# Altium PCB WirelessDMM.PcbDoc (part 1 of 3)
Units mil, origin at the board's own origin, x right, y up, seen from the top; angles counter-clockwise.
Board outline 6000 x 520 mil, 6 copper layers (Layer 1 - Top Layer, Layer 2 - GND, Layer 3 - Signal, Layer 4 - PWR, Layer 5 - GND, Layer 6 - Bottom Layer), stack 63.468 mil thick; 198 components, 117 nets, 636 pads, 272 vias.
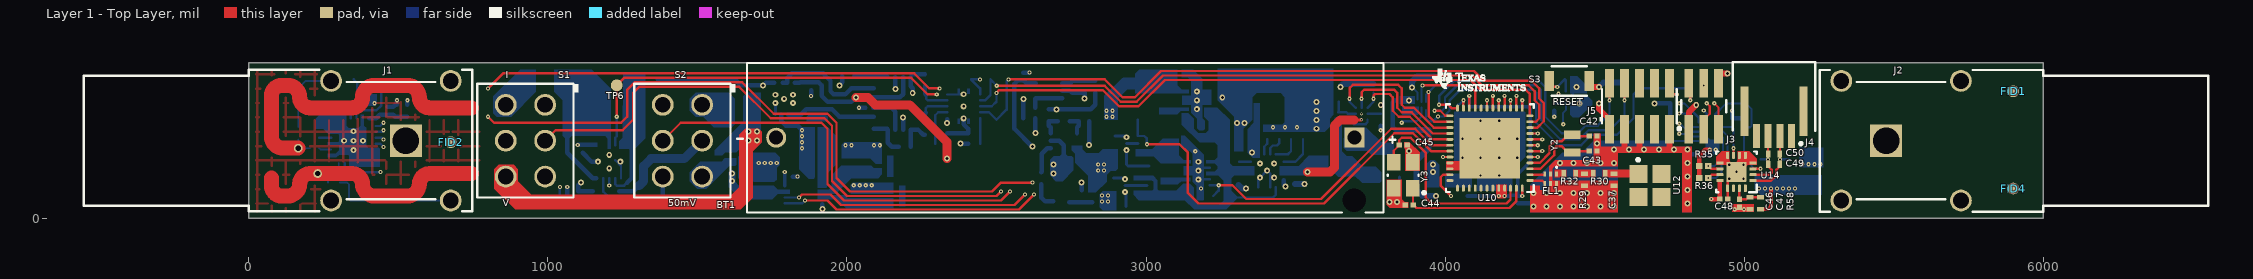
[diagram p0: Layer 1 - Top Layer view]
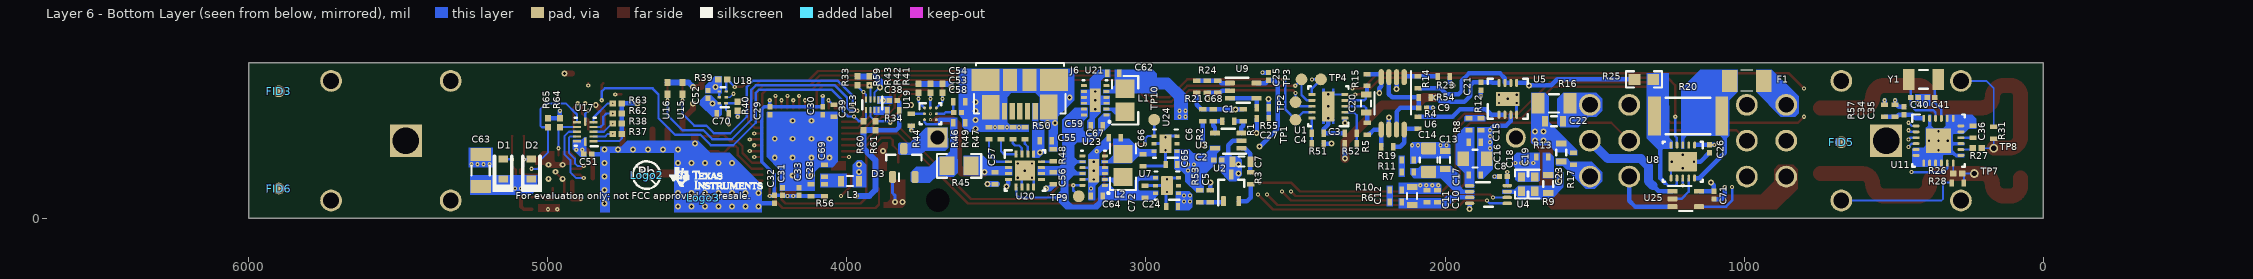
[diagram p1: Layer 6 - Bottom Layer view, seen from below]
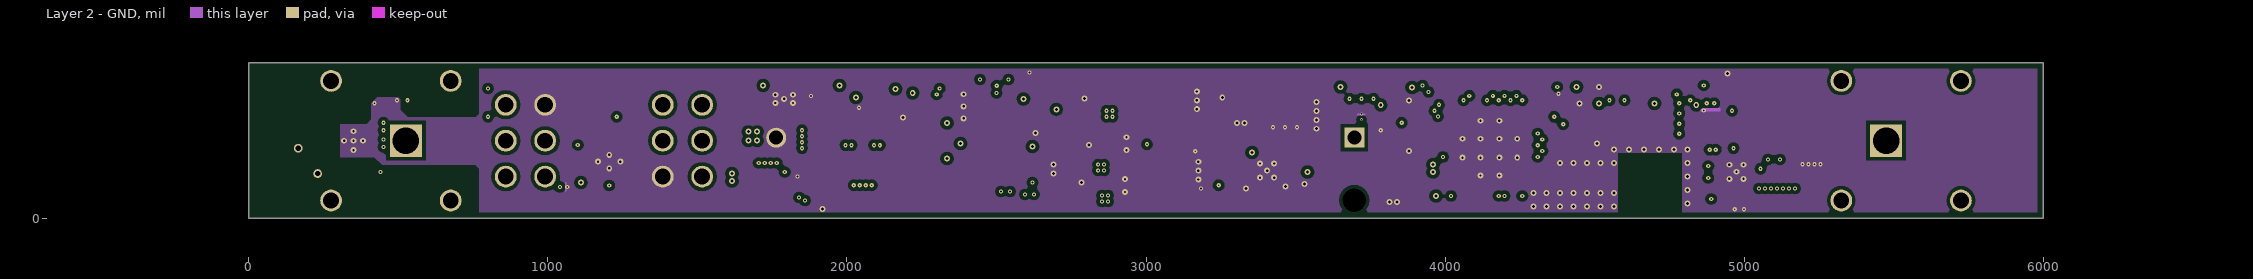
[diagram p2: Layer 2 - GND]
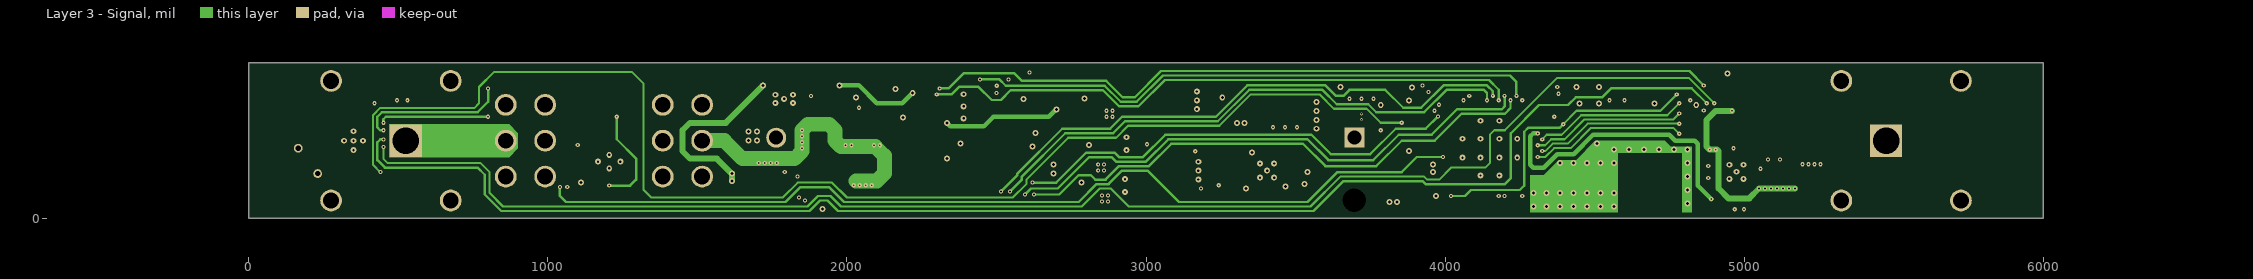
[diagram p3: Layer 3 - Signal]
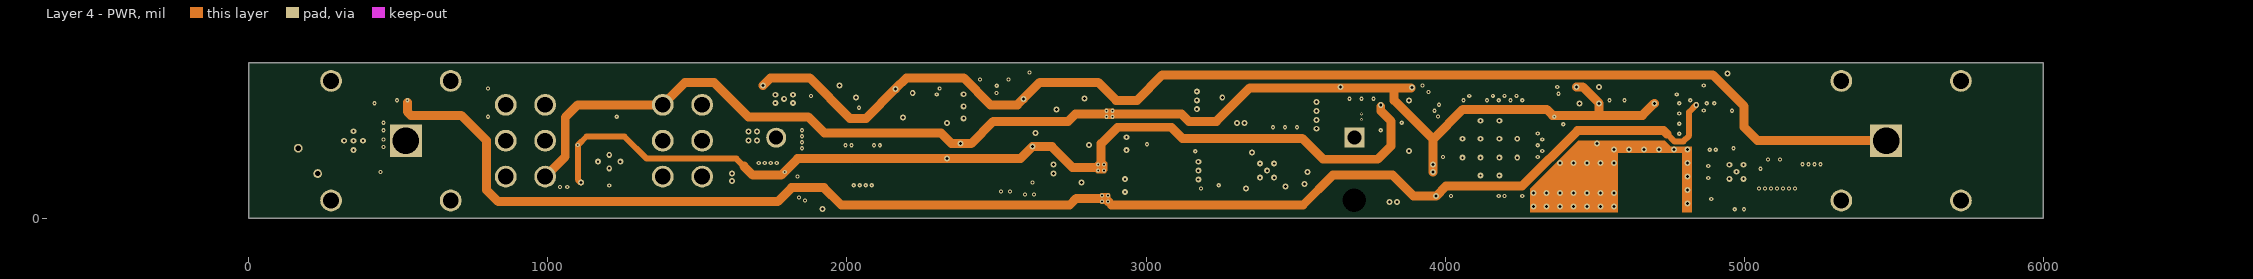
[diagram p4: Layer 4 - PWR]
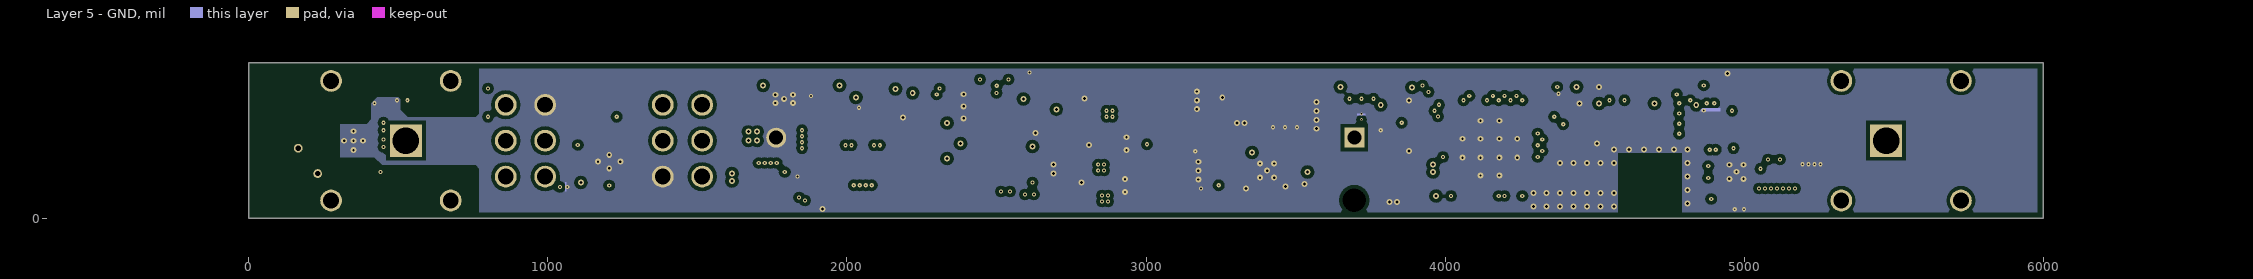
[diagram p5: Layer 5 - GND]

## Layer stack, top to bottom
Top Solder: solder mask 0.4, Solder Resist, Dk 3.5
Layer 1 - Top Layer: signal copper 1.4
Dielectric 1: prepreg 15, 370HR, Dk 4.2
Layer 2 - GND: signal copper 1.417
Dielectric 2: core 10, 370HR, Dk 4.2
Layer 3 - Signal: signal copper 1.417
Dielectric 3: prepreg 5, 370HR, Dk 4.2
Layer 4 - PWR: signal copper 1.417
Dielectric 4: core 10, 370HR, Dk 4.2
Layer 5 - GND: signal copper 1.417
Dielectric 5: prepreg 15, 370HR, Dk 4.2
Layer 6 - Bottom Layer: signal copper 1.4
Bottom Solder: solder mask 0.4, Solder Resist, Dk 3.5

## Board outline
0,0 0,520 6000,520 6000,0

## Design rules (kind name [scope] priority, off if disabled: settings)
AcuteAngle [All] p1: minimum=4.50000000000000E+0001 checktracksonly=FALSE
AssemblyTestPointUsage [All] p1: valid=2
BoardOutlineClearance BoardOutlineClearance_MountingHoles [OnCopper and InComponentClass('Mounting Holes')] p1: gap=40
BoardOutlineClearance BoardOutlineClearance_Poly [OnCopper and InPoly] p2: gap=20
BoardOutlineClearance [OnCopper and Not InComponentClass('Logo') and not InComponentClass('FiducialMark') and not InRegion(1000,500,4000,800)] p3: gap=19
Clearance Clearance_Keepouts [((IsTrack Or IsArc) And Not InPoly) And IsFree and IsKeepOut vs ((IsTrack Or IsArc) And Not InPoly) And IsFree and IsKeepOut] p1: gap=0
Clearance Clearance_Poly [InPolygon] p2: gap=12
Clearance [All] p3: gap=6
ComponentClearance ComponentClearance_MountingHoles_FiducialMarks [InComponentClass('Mounting Holes') vs InComponentClass('FiducialMark')] p1: gap=5 collisioncheckmode=3 verticalgap=10 showdistances=FALSE
ComponentClearance ComponentClearance_Shunt [InComponentClass('Header') vs InComponentClass('Shunt')] p2: gap=0 collisioncheckmode=3 verticalgap=0 showdistances=FALSE
ComponentClearance ComponentClearance_Logo [InComponentClass('Logo')] p3: gap=5 collisioncheckmode=3 verticalgap=10 showdistances=FALSE
ComponentClearance ComponentClearance_ScrewToNut [(HasFootprint('NY PMS 440 0025 PH')) vs (HasFootprint('Keystone_1902C'))] p4: gap=5 collisioncheckmode=3 verticalgap=10 showdistances=FALSE
ComponentClearance ComponentClearance_MountingHoles [InComponentClass('Mounting Holes')] p5: gap=5 collisioncheckmode=3 verticalgap=100000 showdistances=FALSE
ComponentClearance ComponentClearance_SmallPassives [HasFootprint('0201*') or HasFootprint('0402*') or HasFootprint('0508') or HasFootprint('0603*') or HasFootprint('0612') or HasFootprint('0805*') or HasFootprint('0815*') or HasFootprint('0830*') or HasFootprint('1206*') or HasFootprint('1210*') or HasFootprint('1808*') or HasFootprint('1812*') or HasFootprint('1825*') or HasFootprint('2010*') or HasFootprint('2220*') or HasFootprint('2225*') or HasFootprint('2512*') or HasFootprint('2728*') or HasFootprint('3518*') vs HasFootprint('0201*') or HasFootprint('0402*') or HasFootprint('0508') or HasFootprint('0603*') or HasFootprint('0612') or HasFootprint('0805*') or HasFootprint('0815*') or HasFootprint('0830*') or HasFootprint('1206*') or HasFootprint('1210*') or HasFootprint('1808*') or HasFootprint('1812*') or HasFootprint('1825*') or HasFootprint('2010*') or HasFootprint('2220*') or HasFootprint('2225*') or HasFootprint('2512*') or HasFootprint('2728*') or HasFootprint('3518*')] p6: gap=5 collisioncheckmode=3 verticalgap=10 showdistances=FALSE
ComponentClearance ComponentClearance_THtoSMT [IsThruComponent vs IsSMTComponent] p7: gap=5 collisioncheckmode=3 verticalgap=30 showdistances=FALSE
ComponentClearance ComponentClearance_THtoTH [IsThruComponent vs IsThruComponent] p8: gap=5 collisioncheckmode=3 verticalgap=30 showdistances=FALSE
ComponentClearance [All] p9: gap=5 collisioncheckmode=3 verticalgap=10 showdistances=FALSE
DiffPairsRouting [All] p1: maxlimit=100 minlimit=10 mostfreqgap=10 toplayer_minwidth=15 toplayer_maxwidth=15 toplayer_prefwidth=15 midlayer1_minwidth=15 midlayer1_maxwidth=15 midlayer1_prefwidth=15 midlayer2_minwidth=15 midlayer2_maxwidth=15 midlayer2_prefwidth=15 midlayer3_minwidth=15 midlayer3_maxwidth=15 midlayer3_prefwidth=15 midlayer4_minwidth=15 midlayer4_maxwidth=15 midlayer4_prefwidth=15 bottomlayer_minwidth=15 bottomlayer_maxwidth=15 bottomlayer_prefwidth=15 maxuncoupledlength=1000
FabricationTestPointUsage TestPointUsage [All] p1: valid=2 allowmultiple=FALSE
FabricationTestpoint Testpoint [All] p1: side=3 testpointundercomponent=TRUE minsize=40 maxsize=100 preferedsize=60 minholesize=0 maxholesize=40 preferedholesize=32 testpointgrid=1 allowsidetop=TRUE allowsidebottom=TRUE usegrid=TRUE gridtolerance=0.01
FanoutControl Fanout_LCC [IsLCC] p1: bgadir=Out bgaviamode=Centered fanoutstyle=Auto fanoutdirection=Alternating viagrid=1 // Fanout_LCC (Default Rule)
FanoutControl Fanout_BGA [IsBGA] p2: bgadir=Out bgaviamode=Centered fanoutstyle=Auto fanoutdirection=Alternating viagrid=1 // Fanout_BGA (Default Rule)
FanoutControl Fanout_Default [All] p4: bgadir=Out bgaviamode=Centered fanoutstyle=Auto fanoutdirection=Alternating viagrid=1 // Fanout_Default (Default Rule)
FanoutControl Fanout_Small [(CompPinCount < 5)] p5: bgadir=Out bgaviamode=Centered fanoutstyle=Auto fanoutdirection=OutThenIn viagrid=1 // Fanout_Small (Default Rule)
HoleSize [All] p1: absolutevalues=TRUE maxlimit=251 minlimit=6 maxpercent=80.000 minpercent=20.000
MinimumAnnularRing MinimumAnnularRing_ThermalPadVias [IsVia and InAnyComponent] p1: minimumring=5.91
MinimumAnnularRing [All] p2: minimumring=2
MinimumSolderMaskSliver MinimumSolderMaskSliver_Logo [InComponentClass('Logo') vs InComponentClass('Logo')] p1: minsoldermaskwidth=0.7
MinimumSolderMaskSliver [All] p2: minsoldermaskwidth=3.9
NetAntennae [All] p1 off: netantennaetolerance=0
PlaneConnect [All] p1: planeconnectstyle=Relief reliefexpansion=10 reliefentries=4 reliefconductorwidth=10 reliefairgap=10
PolygonConnect [All] p1: connectstyle=Direct reliefconductorwidth=10 reliefentries=4 polygonreliefangle="90 Angle" airgapwidth=10
RoutingVias ThermalPadVias [IsVia and InAnyComponent] p1: holewidth=7.87 width=19.68 viastyle="Through Hole" minholewidth=7.87 minwidth=19.68 maxholewidth=12.99 maxwidth=23.62
RoutingVias [All] p2: holewidth=16 width=34 viastyle="Through Hole" minholewidth=6 minwidth=10 maxholewidth=40 maxwidth=65
SilkToBoardRegionClearance [Not ((IsComment or IsDesignator) And (Hide <> 'False')) and not InRegion(1000,500,4000,800)] p1:
SilkToSilkClearance SilkToSilkClearance_Pb-FreeLogo [(HasFootprint('Pb-Free_Overlay_Medium') OR HasFootprint('Pb-Free_Overlay_Small')) vs (HasFootprint('Pb-Free_Overlay_Medium') OR HasFootprint('Pb-Free_Overlay_Small'))] p1: silktosilkclearance=0
SilkToSilkClearance [All] p2: silktosilkclearance=0.5
SilkToSolderMaskClearance SilkToComponentPadClearance [IsPad and InAnycomponent] p1: minsilkscreentomaskgap=3 clearancetoexposedcopper=TRUE
SilkToSolderMaskClearance "Silk to Solder Mask Opening" [All] p2: minsilkscreentomaskgap=4 clearancetoexposedcopper=FALSE
SolderMaskExpansion [All] p1: expansion=1.97
Width [All] p1: maxlimit=100 minlimit=6 preferedwidth=10 checkconnectedcopper=TRUE
14 further rules are at their usual default settings.

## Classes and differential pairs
component class AssemblyNote: ZZ2 ZZ3 ZZ4
component class FiducialMark: FID1 FID2 FID3 FID4 FID5 FID6
component class WirelessDMM_Hardware: FID1 FID2 FID3 FID4 FID5 FID6 Logo2 Logo3 ZZ2 ZZ3 ZZ4
component class Header: J3 J5
component class WirelessDMM_AFE: C1 C2 C3 C4 C5 C6 C7 C8 C9 C10 C11 C12 C13 C14 C15 C16 C17 C18 C19 C20 C21 C22 C23 C25 C26 C27 C68 C71 C? F1 J1 J2 R1 R2 R3 R4 R5 R6 R7 R8 R9 R10 R11 R12 R13 R14 R15 R16 R17 R19 R20 R21 R23 R24 R25 R28 R31 R51 R52 R53 R54 R55 S1 S2 TP1 TP2 TP3 TP4 TP6 U1 U2 U3 U4 U5 U6 U8 U9 U25
component class WirelessDMM_MCU: C28 C29 C30 C31 C32 C33 C34 C35 C36 C37 C38 C39 C40 C41 C42 C43 C44 C45 C46 C47 C48 C49 C50 C51 C52 C69 C70 FL1 J3 J4 J5 L3 R26 R27 R29 R30 R32 R33 R34 R35 R36 R37 R38 R39 R40 R56 R57 R58 R59 R60 R61 R62 R63 R64 R65 S3 TP7 TP8 U10 U11 U12 U13 U14 U15 U16 U17 U18 Y1 Y2 Y3
component class WirelessDMM_PWR: BT1 C24 C53 C54 C55 C56 C57 C58 C59 C62 C63 C64 C65 C66 C67 C72 D1 D2 D3 J6 L1 L2 R41 R42 R43 R44 R45 R46 R47 R48 R49 R50 TP9 TP10 U7 U19 U20 U21 U23 U24

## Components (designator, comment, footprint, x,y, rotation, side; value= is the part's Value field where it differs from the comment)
BT1 "1021" Keystone_1021 2730,270 r180 top locked
C1 "GRM155R71C104JA88D" 0402S 2725,325 r0 bottom
C2 "CL03A104KP3NNNC" 0201 2760,195 r0 bottom
C3 "GRM155R61A105KE15D" 0402S 2315,285 r180 bottom
C4 "GRM155R61A105KE15D" 0402S 2425,285 r0 bottom
C5 "C1005X5R0J105M050BB" 0402S 2785,75 r90 bottom
C6 "GRM155R60J226ME11D" 0402S 2810,345 r270 bottom
C7 "GRM188R6YA475KE15D" 0603S#1 2681,190 r0 bottom
C8 "CL03A104KP3NNNC" 0201 1805,140 r180 bottom
C9 "CL03A104KP3NNNC" 0201 2075,370 r0 bottom
C10 "C0402C122J5GACTU" 0402S 2025,75 r270 bottom
C11 "C0402C122J5GACTU" 0402S 2060,75 r270 bottom
C12 "C0603C104J5RACTU" 0603S#1 2110,75 r270 bottom
C13 "C0603C100F5GAC7867" 0603S#1 2000,195 r270 bottom
C14 "C0805C103F1GACTU" 0805_HV1 2055,195 r270 bottom
C15 "GRM1555C1H331FA01J" 0402S 1900,255 r0 bottom
C16 "08055A471FAT2A" 0805_HV1 1900,200 r0 bottom
C17 "GRM1555C1H151JA01D" 0402S 1900,145 r0 bottom
C18 "Used in BOM report" 0402 1745,115 r270 bottom
C19 "Used in BOM report" 0402 1700,115 r270 bottom
C20 "GRM1885C1H222JA01D" 0603S#1 2264,384 r270 bottom
C21 "CL03A104KP3NNNC" 0201 1880,442 r90 bottom
C22 "C1608C0G2A101F080AA" 0603S#2 1575,345 r90 bottom
C23 "C1608X7R2A223K" 0603S#1 1611.38,220.21 r90 bottom
C24 "GRM155R61A105KE15D" 0402S 2913,40 r0 bottom
C25 "CL03A104KP3NNNC" 0201 2590,475 r270 bottom
C26 "CL03A104KP3NNNC" 0201 1116,233 r90 bottom
C27 "C1005X5R0J105M050BB" 0402S 2610,334.7 r0 bottom
C28 "GRM155R61A105KE15D" 0402S 4120,95 r90 bottom
C29 "CL03A104KP3NNNC" 0201 4258,360.35 r270 bottom
C30 "CL03A104KP3NNNC" 0201 4081,360 r270 bottom
C31 "CL03A104KP3NNNC" 0201 4215,90 r90 bottom
C32 "CL03A104KP3NNNC" 0201 4243,64 r270 bottom
C33 "CL03A104KP3NNNC" 0201 4160,90 r90 bottom
C34 "C1005X5R1A475K050BC" 0402S 495,360 r90 bottom
C35 "CL03A104KP3NNNC" 0201 465,360 r90 bottom
C36 "GRM155R61A105KE15D" 0402S 235,290 r90 bottom
C37 "GRM1555C1H390JA01D" 0402S 4565.13,130 r270 top
C38 "CL03A104KP3NNNC" 0201 3845,395 r180 bottom
C39 "C1005X5R0J105M050BB" 0402S 4043,360 r270 bottom
C40 "GCM0335C1E220JD03D" 0201_033 430.01,405 r180 bottom
C41 "GCM0335C1E220JD03D" 0201_033 375.01,405 r0 bottom
C42 "GRM0335C1H120JA01D" 0201 4495,275 r180 top
C43 "GRM0335C1H120JA01D" 0201 4495,225 r0 top
C44 "GRM0335C1H120JA01D" 0201 3880,45 r180 top
C45 "GRM0335C1H120JA01D" 0201 3860,245 r0 top
C46 "CL03A104KP3NNNC" 0201 4984.47,51.09 r270 top
C47 "GRM155R61A105KE15D" 0402S 5019.47,51.09 r270 top
C48 "GRM033R60J474KE90D" 0201_033 4932,65 r0 top
C49 "GRM1555C1H390JA01D" 0402S 5100,180 r180 top
C50 "GRM1555C1H390JA01D" 0402S 5100,215 r180 top
C51 "CL03A104KP3NNNC" 0201 4867,215 r0 bottom
C52 "CL03A104KP3NNNC" 0201 4465,415 r270 bottom
C53 "GRM033R60J474KE90D" 0201_033 3630,355 r180 bottom
C54 "GRM155R61C225KE11D" 0402S 3625,390 r180 bottom
C55 "GRM155R61A105KE15D" 0402S 3335,260 r0 bottom
C56 "C1005X5R1A475K050BC" 0402S 3310,135 r270 bottom
C57 "C1005X5R1A475K050BC" 0402S 3505,135 r270 bottom
C58 "GRM155R61A105KE15D" 0402S 3625,320 r180 bottom
C59 "CL05A106MP5NUNC" 0402S 3165,310 r0 bottom
C62 "CL05A106MP5NUNC" 0402S 3110,485.28 r0 bottom
C63 "C3216X5R1A107M160AC" 1206_190L 5225,160 r90 bottom
C64 "CL05A106MP5NUNC" 0402S 3165,75 r0 bottom
C65 "GRM155R61A105KE15D" 0402S 2914.74,180 r0 bottom
C66 "GRM155R61A105KE15D" 0402S 3010,195 r270 bottom
C67 "CL05A106MP5NUNC" 0402S 3105,270 r0 bottom
C68 "C1005X5R0J105M050BB" 0402S 2760,440 r270 bottom
C69 "GRM155R61A105KE15D" 0402S 4075,160 r90 bottom
C70 "CL05A225KQ5NNNC" 0402S 4415,350 r0 bottom
C71 "CL03A104KP3NNNC" 0201 1101,78 r90 bottom
C72 "GRM155R61A105KE15D" 0402S 3003,90 r90 bottom
D1 "CDBU0130L" SOD-523F 5150,165 r90 bottom
D2 "CDBU0130L" SOD-523F 5055,165 r90 bottom
D3 "SI2323DS" SOT-23 3860,176 r180 bottom
F1 "NANOSMDC020F-2" FUSE_NANO02 991,460 r0 bottom
FID1 "Fiducial" Fiducial10-20 5900,425 r0 top
FID2 "Fiducial" Fiducial10-20 675,255 r0 top
FID3 "Fiducial" Fiducial10-20 5900,425 r180 bottom
FID4 "Fiducial" Fiducial10-20 5900,100 r0 top
FID5 "Fiducial" Fiducial10-20 675,255 r180 bottom
FID6 "Fiducial" Fiducial10-20 5900,100 r180 bottom
FL1 "LFB182G45BG5D920" Murata_LFB182G45BG5D920 4353,133 r270 top
J1 "66.9040-22" Multi-Contact_66_9040-22 475,260 r180 top locked
J2 "66.9040-21" Multi-Contact_66_9040-21 5525,260 r0 top locked
J3 "20021121-00006C4LF" FCI_20021121-00006x4 4865,375 r90 top
J4 "HFW4R-1STE1LF" HFW4R-1STE1LF 5100,317 r180 top locked
J5 "20021121-00010C4LF" FCI_20021121-00010xxLF 4650,375 r90 top
J6 "0473460001" CONN_47346-0001 3422,520 r180 bottom locked
L1 "MLZ2012A2R2WT000" 0805M 3070,395 r90 bottom
L2 "MLZ2012A2R2WT000" 0805M 3077,177 r90 bottom
L3 "BLM18HE152SN1D" 0603S#1 3990,125 r0 bottom
Logo2 "Pb-Free Symbol" Pb-Free_Overlay_Small 4670,145 r180 bottom
Logo3 "FCC disclaimer" FCC_disclaimer 4480,70 r180 bottom
R1 "CRCW040213K3FKED" 0402S 2675,345 r90 bottom
R2 "CRCW04028R20JNED" 0402S 2775,345 r90 bottom
R3 "CRCW040210K0FKED" 0402S 2650,135 r90 bottom
R4 "CRCW04023K01FKED" 0402S 2090,320 r270 bottom
R5 "CRCW040252R3FKED" 0402S 2260,300 r90 bottom
R6 "CRCW04029K76FKED" 0402S 2165,55 r180 bottom
R7 "RG1005P-104-B-T5" 0402S 2125,155 r180 bottom
R8 "CRCW04021M00FKED" 0402S 1920,315 r270 bottom
R9 "CRCW0603100MJPEAHR" 0603S#1 1655,115 r270 bottom
R10 "CRCW040210R0FKED" 0402S 2165,95 r0 bottom
R11 "CRCW04020000Z0ED" 0402S 2125,195 r0 bottom
R12 "CRCW040210K2FKED" 0402S 1880,315 r90 bottom
R13 "CRCW04020000Z0ED" 0402S 1675,205 r180 bottom
R14 "CRCW04023K01FKED" 0402S 2090,455 r270 bottom
R15 "CRCW040252R3FKED" 0402S 2261,463 r270 bottom
R16 "CRHV1206AF10M0FKE5" 1206L 1636,385 r180 bottom
R17 "CRCW0402499KFKED" 0402S 1570,200 r90 bottom
R19 "CRCW0402133KFKED" 0402S 2193.39,240 r180 bottom
R20 "CRCW251295R3FKEG" 2512L 1187,343 r180 bottom
R21 "CRCW040211K3FKED" 0402S 2830,440 r270 bottom
R23 "CRCW0402133KFKED" 0402S 2005,475 r180 bottom
R24 "CRCW040213K3FKED" 0402S 2795,440 r90 bottom
R25 "RL0603FR-070R5L" 0603 1335,465 r180 bottom
R26 "CRCW0201909RFKED" 0201M 285,150 r0 bottom
R27 "CRCW0201909RFKED" 0201M 220,235 r0 bottom
R28 "MCR01MZPJ000" 0402S 285,119 r180 bottom
R29 "MCR01MZPJ000" 0402S 4466,130 r90 top
R30 "MCR01MZPJ000" 0402S 4515,150 r180 top
R31 "MCR01MZPJ000" 0402S 165,286 r270 bottom
R32 "MCR01MZPJ000" 0402S 4417,150 r180 top
R33 "RK73H1HTTC4702F" 0201M 3965,460 r90 bottom
R34 "CRCW0402200KFKED" 0402S 3845,360 r0 bottom
R35 "RK73H1HTTC4702F" 0201M 4865,175 r180 top
R36 "RK73H1HTTC4702F" 0201M 4865,135 r180 top
R37 "RK73H1HTTC4702F" 0201M 4768,283 r0 bottom
R38 "RK73H1HTTC4702F" 0201M 4768,317 r0 bottom
R39 "CRCW0201100KFKED" 0201M 4415,465 r0 bottom
R40 "CRCW02011K00FKED" 0201M 4365,375 r270 bottom
R41 "CRCW020110K0FKED" 0201M 3680.85,435 r90 bottom
R42 "CRCW020110K0FKED" 0201M 3720.85,435 r90 bottom
R43 "CRCW020110K0FKED" 0201M 3760.85,435 r90 bottom
R44 "ERJ-2RKF1002X" 0402S 3785,330 r270 bottom
R45 "WSL0805R0100FEA18" 0805_HV 3625,176 r180 bottom
R46 "CRCW040210K0JNED" 0402S 3525,285 r270 bottom
R47 "CRCW04021K15FKED" 0402S 3445,285 r270 bottom
R48 "CRCW04029K31FKED" 0402S 3310,212 r270 bottom
R49 "CRCW04025K76FKED" 0402S 3485,285 r270 bottom
R50 "CRCW040230K1FKED" 0402S 3405,285 r270 bottom
R51 "MCR01MZPJ000" 0402S 2425,250 r180 bottom
R52 "MCR01MZPJ000" 0402S 2315,250 r0 bottom
R53 "MCR01MZPJ000" 0402S 2820,75 r90 bottom
R54 "MCR01MZPJ000" 0402S 2068,405 r180 bottom
R55 "CRCW04021K00JNED" 0402S 2610,370 r0 bottom
R56 "MCR01MZPJ000" 0402S 4075,95 r90 bottom
R57 "MCR01MZPJ000" 0402S 530,360 r90 bottom
R58 "MCR01MZPJ000" 0402S 5054.47,51.09 r270 top
R59 "RK73H1HTTC4702F" 0201M 3925,460 r90 bottom
R60 "RK73H1HTTC4702F" 0201M 3945,310 r90 bottom
R61 "RK73H1HTTC4702F" 0201M 3905,310 r270 bottom
R62 "RK73H1HTTC4702F" 0201M 4768,351 r180 bottom
R63 "RK73H1HTTC4702F" 0201M 4768,385 r180 bottom
R64 "RK73H1HTTC4702F" 0201M 4960,320 r90 bottom
R65 "47.0k" 0201M 5000,320 r90 bottom
S1 "GS-113-0043" SW_GS-113-0043 925,260 r270 top
S2 "GS-113-0043" SW_GS-113-0043 1450,260 r270 top
S3 "B3U-1000P" SW_B3U-1000P 4415,460 r180 top
TP1 "TESTPOINT" TP_SM_1MM 2500,330 r0 bottom
TP2 "TESTPOINT" TP_SM_1MM 2500,389 r270 bottom
TP3 "TESTPOINT" TP_SM_1MM 2480,465 r270 bottom
TP4 "TESTPOINT" TP_SM_1MM 2415,465 r270 bottom
TP6 "TESTPOINT" TP_SM_1MM 1230,445 r270 top
TP7 "TESTPOINT" TP_H045P075 230,150 r270 bottom
TP8 "TESTPOINT" TP_H045P075 165,235 r270 bottom
TP9 "TESTPOINT" TP_SM_1MM 3225,74 r270 bottom
TP10 "TESTPOINT" TP_SM_1MM 2972.74,330 r270 bottom
U1 "ADS8885IDRCR" DRC0010D 2390,375 r0 bottom
U2 "REF3325AIDCKTG4" DCK0003A_N 2715,102 r90 bottom
U3 "OPA313IDCKR" DCK0005A_N 2725,260 r0 bottom
U4 "TS5A3359DCUR" DCU0008A_N 1855,80 r180 bottom
U5 "OPA2313IDRGR" DRG0008A 1790,400 r90 bottom
U6 "THS4531IDGK" DGK0008A_N 2175,385 r270 bottom
U7 "TPS78230DRVR" DRV0006A 2930,110 r0 bottom
U8 "TS3A24159DRCR" DRC0010J 1205,190 r270 bottom
U9 "OPA333AIDCKR" DCK0005A_N 2675,427.22 r180 bottom
U10 "CC2640F128RGZR" RGZ0048A 4150,235 r45 top locked
U11 "MSP430FR2532IRGER" RGE0024G 350,260 r180 bottom
U12 "479480001" Molex_0479480001 4685,110 r0 top locked
U13 "LSF0102DQER" DQE0008A 3915,380 r270 bottom
U14 "RF430CL330HIRGTR" RGT0016C#1 4974.47,156.09 r180 top
U15 "TPD1E10B06DPYR" DPY0002A 4550,435 r90 bottom
U16 "TPD1E10B06DPYR" DPY0002A 4600,435 r90 bottom
U17 "LSF0204RUTR" RUT0012A 4875,290 r0 bottom
U18 "TPS3422EGDRYR" DRY0006A 4415,405 r0 bottom
U19 "BQ27426YZFR" YZF0009-C01 3720.85,350 r180 bottom
U20 "BQ24232RGTR" RGT0016C#2 3405,160 r180 bottom
U21 "TPS62740DSSR" DSS0012A 3170,395 r0 bottom
U23 "TPS62740DSSR" DSS0012A 3175,160 r0 bottom
U24 "TPS78227DRVR" DRV0006A 2935,250 r0 bottom
U25 "TS5A3166DCKR" DCK0005A_N 1195,65.31 r180 bottom
Y1 "FC-135 32.7680KA-A3" Epson_FC-135 400.01,465 r180 bottom
Y2 "FC-12M 32.7680KA-A3" Epson_FC-12M 4425,250 r90 top
Y3 "TSX-3225 24.0000MF20G-AC3" EPSON_TSX-3225 3860,145 r180 top
ZZ2 "These assemblies are ESD sensitive, ESD precautions shall be observed." AssemblyNote 200,900 r0 top
ZZ3 "These assemblies must be clean and free from flux and all contaminants. Use of no clean flux is not acceptable." AssemblyNote 200,800 r0 top
ZZ4 "These assemblies must comply with workmanship standards IPC-A-610 Class 2, unless otherwise specified." AssemblyNote 200,700 r0 top

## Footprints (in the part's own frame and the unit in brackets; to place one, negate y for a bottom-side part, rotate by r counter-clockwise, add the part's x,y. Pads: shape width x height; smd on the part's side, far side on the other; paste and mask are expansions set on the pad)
0201 [mm] "Data from Kemet datasheet CC101_COM dated 7/28/11"
  rect 0.46x0.42 smd mask+0.048: 1(-0.33,0) 2(0.33,0)
  body extent -0.31,-0.16 0.31,0.16, height 0.26
0201_033 [mm] "SMD, 2-Leads, Height 0.33mm"
  rect 0.46x0.42 smd mask+0.048: 1(-0.33,0) 2(0.33,0)
  body extent -0.31,-0.16 0.31,0.16, height 0.33
0201M [mm] "Data from Kemet datasheet CC101_COM dated 7/28/11"
  rect 0.56x0.52 smd mask+0.048: 1(-0.38,0) 2(0.38,0)
  body extent -0.31,-0.16 0.31,0.16, height 0.26
0402 [mm] "0402 from SM-752 data"
  rect 0.8x0.6 smd: 1(-0.6,0) 2(0.6,0)
  silkscreen extent -1.22,-0.52 1.22,0.52, body extent -0.55,-0.3 0.55,0.3, height 0.6
0402S [mil] "Based on C0402S footprint from PADS legacy"
  rect 15x24 smd: 1(-20,0) 2(20,0)
  body extent -22,-12 22,12, height 24
0603 [mm] "0603 from SM-752 data"
  rect 1x0.95 smd: 1(-0.8,0) 2(0.8,0)
  silkscreen extent -1.52,-0.69 1.52,0.69, body extent -0.87,-0.47 0.87,0.47, height 1
0603S#1 [mil]
  rect 20x35 smd: 1(-30,0) 2(30,0)
  silkscreen extent -10,-17 10,17, body extent -34,-19 34,19, height 39
0603S#2 [mil]
  rect 35x20 smd: 1(-20,90) 2(-20,30)
  silkscreen extent -37,50 -3,70, body extent -39,26 -1,94, height 39
0805_HV [mil] "0805 with 30mil clearance between pads"
  rect 50x63 smd: 1(-40,0) 2(40,0)
  silkscreen extent -74,-40 74,40, body extent -43,-29 43,29, height 57
0805_HV1 [mm] "Custom footprint based on analyzing multiple manufacturer recommendations"
  rrect10% 1x1.25 smd: 1(-1,0) 2(1,0)
  silkscreen extent -0.2,-0.75 0.2,0.75, body extent -1.1,-0.72 1.1,0.73, height 1.45
0805M [mm] "0805 from SM-752 data"
  rect 1.55x1.6 smd: 1(-0.975,0) 2(0.975,0)
  silkscreen extent -2.07,-1.12 2.07,1.12, body extent -1.1,-0.72 1.1,0.72, height 1.45
1206_190L [mm] "1206_190"
  rect 1.1x1.75 smd: 1(-1.35,0) 2(1.35,0)
  silkscreen extent -0.4,-0.77 0.4,0.77, body extent -1.75,-0.95 1.75,0.95, height 1.9
1206L [mm] "1206 from SM-752 data"
  rect 1.1x1.75 smd: 1(-1.35,0) 2(1.35,0)
  silkscreen extent -0.4,-0.77 0.4,0.77, body extent -1.7,-0.9 1.7,0.9, height 1.35
2512L [mm] "Chip Resistor, Body 6.3x3.2mm, IPC High Density"
  rect 1.1x3.3 smd: 1(-2.85,0) 2(2.85,0)
  silkscreen extent -1.9,-1.55 1.9,1.55, body extent -3.22,-1.67 3.22,1.67, height 0.71
AssemblyNote [mil] "Assembly Note"
CONN_47346-0001 [mm] "MOLEX"
  rect 0.45x1.38 smd mask+0.025: 1(1.3,-4.105) 2(0.65,-4.105) 3(0,-4.105) 4(-0.65,-4.105) 5(-1.3,-4.105)
  rect 1.475x2.1 smd mask+0.025: 6(-2.462,-3.755) 11(2.463,-3.75)
  rect 2.375x1.9 smd mask+0.025: 7(-2.912,-1.45) 10(2.912,-1.45)
  rect 1.175x1.9 smd mask+0.025: 8(-0.837,-1.45) 9(0.837,-1.45)
  silkscreen extent -3.9,-4.28 3.9,0, body extent -3.99,-4.43 3.99,1, height 2.72
DCK0003A_N [mm] "SOT23, 3-Leads, Body 2.0x1.25mm, Pitch 0.65mm, Lead Span 2.1mm, IPC Medium Density"
  rrect25% 0.85x0.4 smd: 1(-1.125,0.65) 2(-1.125,-0.65) 3(1.125,0)
  silkscreen extent -1.48,-1.1 0.7,1.1, body extent -1.06,-1 1.06,1, height 1.1
DCK0005A_N [mm] "SOT353, 5-Leads, Body 2x1.3mm, Pitch 0.65mm, Lead Span 2.1mm, IPC Medium Density"
  rrect25% 0.85x0.4 smd: 1(-1.125,0.65) 2(-1.125,0) 3(-1.125,-0.65) 4(1.125,-0.65) 5(1.125,0.65)
  silkscreen extent -1.48,-1.02 0.55,1.1, body extent -1.14,-1 1.14,1, height 0.95
DCU0008A_N [mm] "TSSOP, 8-Leads, Body 2x2.3mm, Pitch 0.5mm, IPC Medium Density"
  oval 0.8x0.3 smd: 1(-1.6,0.75) 2(-1.6,0.25) 3(-1.6,-0.25) 4(-1.6,-0.75) 5(1.6,-0.75) 6(1.6,-0.25) 7(1.6,0.25) 8(1.6,0.75)
  silkscreen extent -1.05,-1.05 0.38,1.05, body extent -1.56,-1 1.56,1, height 0.9
DGK0008A_N [mm] "TSOP, 8-Leads, Body 3x3mm, Pitch 0.65mm, IPC Medium Density"
  oval 1.35x0.45 smd: 1(-2.225,0.975) 2(-2.225,0.325) 3(-2.225,-0.325) 4(-2.225,-0.975) 5(2.225,-0.975) 6(2.225,-0.325) 7(2.225,0.325) 8(2.225,0.975)
  silkscreen extent -2.75,-1.55 0.95,1.55, body extent -2.45,-1.5 2.45,1.5, height 0.96
DPY0002A [mm] "R-PX2SON-N2"
  rect 0.6x0.5 smd: 1(-0.5,0) 2(0.5,0)
  body extent -0.55,-0.35 0.55,0.35, height 0.4
DQE0008A [mm] "SON, 8-Leads, Body 1.4x1mm, Pitch 0.35mm, TI Recommended"
  rect 0.6x0.16 smd mask+0.025: 1(-0.4,0.525)
  rect 0.5x0.16 smd mask+0.025: 2(-0.45,0.175) 3(-0.45,-0.175) 4(-0.45,-0.525) 5(0.45,-0.525) 6(0.45,-0.175) 7(0.45,0.175) 8(0.45,0.525)
  silkscreen extent -0.7,-0.85 0.4,0.85, body extent -0.53,-0.72 0.53,0.73, height 0.41
DRC0010D [mm] "SON, 10-Leads, Body 3x3mm, Pitch 0.5mm, Thermal Pad 2.55x1.05mm"
  rrect42% 0.6x0.24 smd: 1(-1.4,1) 2(-1.4,0.5) 3(-1.4,0) 4(-1.4,-0.5) 5(-1.4,-1) 6(1.4,-1) 7(1.4,-0.5) 8(1.4,0) 9(1.4,0.5) 10(1.4,1)
  rrect10% 1.05x2.55 smd paste-0.825: 11(0,0)
  Layer 1 - Top Layer region: 0.525,-1.505 0.295,-1.505 0.295,-1.05 0.525,-1.05
  Layer 1 - Top Layer region: -0.525,-1.05 -0.295,-1.05 -0.295,-1.505 -0.525,-1.505
  Layer 1 - Top Layer region: -0.525,1.505 -0.295,1.505 -0.295,1.05 -0.525,1.05
  Layer 1 - Top Layer region: 0.525,1.05 0.295,1.05 0.295,1.505 0.525,1.505
  silkscreen extent -1.7,-1.7 1.7,1.7, body extent -1.55,-1.55 1.55,1.55, height 1.01
DRC0010J [mm] "SON, 10-Leads, Body 3x3mm, Pitch 0.5mm, Thermal Pad 2.4x1.65mm, TI Recommended"
  rrect100% 0.6x0.24 smd: 1(-1.4,1) 2(-1.4,0.5) 3(-1.4,0) 4(-1.4,-0.5) 5(-1.4,-1) 6(1.4,-1) 7(1.4,-0.5) 8(1.4,0) 9(1.4,0.5) 10(1.4,1)
  rrect6% 1.65x2.4 smd paste-0.825: 11(0,0)
  silkscreen extent -1.7,-1.7 1.7,1.7, body extent -1.5,-1.5 1.5,1.5, height 0.77
DRG0008A [mm] "SON, 8-Leads, Body 3x3mm, Pitch 0.5mm, Thermal Pad 2x1.2mm, TI Recommended"
  oval 0.7x0.25 smd: 1(-1.35,0.75) 2(-1.35,0.25) 3(-1.35,-0.25) 4(-1.35,-0.75) 5(1.35,-0.75) 6(1.35,-0.25) 7(1.35,0.25) 8(1.35,0.75)
  rect 1.2x2 smd paste-0.6: 9(0,0)
  Drill Guide keep-out region: -0.6,1.3 0.6,1.3 0.6,1 -0.6,1
  Drill Guide keep-out region: 0.6,-1.3 -0.6,-1.3 -0.6,-1 0.6,-1
  silkscreen extent -1.7,-1.7 1.7,1.7, body extent -1.55,-1.55 1.55,1.55, height 0.81
DRV0006A [mm] "SON, 6-Leads, Body 2x2mm, Pitch 0.65mm, Thermal Pad 1.6x1mm, TI Recommended"
  rrect33% 0.45x0.3 smd: 1(-0.975,0.65) 2(-0.975,0) 3(-0.975,-0.65) 4(0.975,-0.65) 5(0.975,0) 6(0.975,0.65)
  rrect14% 1x0.7 on Bottom Paste: 7(0,-0.45) 7(0,0.45)
  rrect10% 1x1.6 smd paste-0.5: 7(0,0)
  silkscreen extent -1.05,-1.2 1.05,1.2, body extent -1.05,-1.05 1.05,1.05, height 0.81
DRY0006A [mm] "PSON, 6-Leads, Body 1x1.45mm, Pitch 0.5mm, TI Recommended"
  rect 0.35x0.2 smd: 1(-0.275,0.5)
  rect 0.3x0.2 smd: 2(-0.3,0) 3(-0.3,-0.5) 4(0.3,-0.5) 5(0.3,0) 6(0.3,0.5)
  silkscreen extent -0.5,-0.85 0.2,0.85, body extent -0.53,-0.75 0.53,0.75, height 0.61
DSS0012A [mm] "SON, 12-Leads, Body 2x3mm, Pitch 0.5mm, Thermal Pad 2x0.9mm, TI Recommended"
  rrect40% 0.5x0.25 smd: 1(-0.95,1.25) 2(-0.95,0.75) 3(-0.95,0.25) 4(-0.95,-0.25) 5(-0.95,-0.75) 6(-0.95,-1.25) 7(0.95,-1.25) 8(0.95,-0.75) 9(0.95,-0.25) 10(0.95,0.25) 11(0.95,0.75) 12(0.95,1.25)
  rrect11% 0.9x0.9 on Bottom Paste: 13(0,-0.55) 13(0,0.55)
  rrect11% 0.9x2 smd paste-0.45: 13(0,0)
  silkscreen extent -1.05,-1.7 1.05,-1.7, body extent -1,-1.5 1,1.5, height 0.8
Epson_FC-12M [mm] "Epson"
  rect 0.7x1.4 smd: 1(-0.75,0) 2(0.75,0)
  body extent -1.05,-0.63 1.05,0.63, height 0.6
Epson_FC-135 [mm] "SMD, 2-Leads, Body 3.2x1.5mm"
  rect 1x1.8 smd: 1(-1.25,0) 2(1.25,0)
  silkscreen extent -0.35,-0.8 0.35,0.8, body extent -1.65,-0.8 1.65,0.8, height 0.9
EPSON_TSX-3225 [mm] "SMD, 4-Leads, Body 2.65x3.35mm, Height 0.6mm"
  rect 1.15x1.4 smd: 1(-0.8,1.1) 2(-0.8,-1.1) 3(0.8,-1.1) 4(0.8,1.1)
  silkscreen extent -1.9,-0.05 1.33,1.62, body extent -1.33,-1.68 1.33,1.68, height 0.61
FCC_disclaimer [mil]
FCI_20021121-00006x4 [mm] "Header, 1.27mm, 3x2, SMT"
  rect 2.4x0.76 smd: 1(-1.95,1.27) 2(1.95,1.27) 3(-1.95,0) 4(1.95,0) 5(-1.95,-1.27) 6(1.95,-1.27)
  silkscreen extent -2.03,-1.9 0.5,2.21, body extent -2.75,-1.91 2.75,1.9, height 4.5
FCI_20021121-00010xxLF [mm] "Header, 1.27mm, 5x2, SMT"
  rect 2.4x0.76 smd: 1(-1.95,2.54) 2(1.95,2.54) 3(-1.95,1.27) 4(1.95,1.27) 5(-1.95,0) 6(1.95,0) 7(-1.95,-1.27) 8(1.95,-1.27) 9(-1.95,-2.54) 10(1.95,-2.54)
  silkscreen extent -1.44,-3.17 1.44,3.4, body extent -2.75,-3.17 2.75,3.18, height 4.5
Fiducial10-20 [mm]
  round 1 smd mask+0.5: 1(0,0)
FUSE_NANO02 [mm] "SMD, Body 3.2x1.585mm"
  rect 1.3x1.85 smd: 1(-1.45,0) 2(1.45,0)
  silkscreen extent -0.5,-0.9 0.5,0.9, body extent -1.7,-0.9 1.7,0.9, height 0.82
HFW4R-1STE1LF [mm] "CONN FFC BOTTOM 4POS 1.00MM R/A"
  rect 0.6x2 smd: 1(-1.5,1.05) 2(-0.5,1.05) 3(0.5,1.05) 4(1.5,1.05)
  rect 0.7x4.2 smd: M1(-2.5,-1.05) M2(2.5,-1.05)
  silkscreen extent -3.5,-5.25 3.5,1.78, body extent -3.4,-5.15 3.4,0.55, height 2.01
Keystone_1021 [mm] "HOLDER BATTERY AAA, TH"
  rect 1.7x1.7 hole 1.19: 1(-24.55,0)
  round 1.7 hole 1.19: 2(24.55,0)
  rect 0x0 hole 1.98 unplated: ALIGN(-24.55,5.31)
  silkscreen extent -28.05,-6.35 27.87,6.35, body extent -27.03,-6.35 27.04,6.35, height 11.18
Molex_0479480001 [mm] "SMD, 4-Leads, Body 3.14x3.14mm"
  rect 1.54x1.54 smd: 1(-0.97,0.97) 2(-0.97,-0.97) 3(0.97,-0.97) 4(0.97,0.97)
  silkscreen extent -1.12,2.07 -0.87,2.31, body extent -1.57,-1.57 1.57,1.57, height 4
Multi-Contact_66_9040-21 [mm] "XELW-4 Connector, TH"
  rect 2.75x2.75 hole 2.25: 1(-1.28,0)
  round 1.85 hole 1.35: 2(-5.08,5.08) 3(-5.08,-5.08) 4(5.08,-5.08) 5(5.08,5.08)
  silkscreen extent -6.92,-6.02 26.08,6, body extent -6.92,-6.02 26.08,6, height 12.31
Multi-Contact_66_9040-22 [mm] "XELW-4 Connector, TH"
  rect 2.75x2.75 hole 2.25: 1(-1.28,0)
  round 1.85 hole 1.35: 2(-5.08,5.08) 3(-5.08,-5.08) 4(5.08,-5.08) 5(5.08,5.08)
  silkscreen extent -6.92,-6.02 26.08,6, body extent -6.92,-6.02 26.08,6, height 12.31
Murata_LFB182G45BG5D920 [mm] "SMT, 6-Leads, Body 1.6x0.8mm, Pitch 0.5mm"
  rect 0.425x0.25 smd mask+0.07: 1(-0.413,0.5) 2(-0.413,0) 3(-0.413,-0.5) 4(0.412,-0.5) 5(0.412,0) 6(0.412,0.5)
  silkscreen extent -0.98,0.5 -0.96,0.52, body extent -0.45,-0.85 0.45,0.85, height 0.65
Pb-Free_Overlay_Small [mil]
  silkscreen extent -46,-46 46,46
RGE0024G [mm] "QFN, 24-Leads, Body 4x4mm, Pitch 0.5mm, Thermal Pad 2.1x2.1mm, TI Recommended"
  oval 0.6x0.24 smd: 1(-1.9,1.25) 2(-1.9,0.75) 3(-1.9,0.25) 4(-1.9,-0.25) 5(-1.9,-0.75) 6(-1.9,-1.25) 13(1.9,-1.25) 14(1.9,-0.75) 15(1.9,-0.25) 16(1.9,0.25) 17(1.9,0.75) 18(1.9,1.25)
  oval 0.24x0.6 smd: 7(-1.25,-1.9) 8(-0.75,-1.9) 9(-0.25,-1.9) 10(0.25,-1.9) 11(0.75,-1.9) 12(1.25,-1.9) 19(1.25,1.9) 20(0.75,1.9) 21(0.25,1.9) 22(-0.25,1.9) 23(-0.75,1.9) 24(-1.25,1.9)
  rect 2.1x2.1 smd paste-1.05: 25(0,0)
  silkscreen extent -2.22,-2.22 2.22,2.22, body extent -2.07,-2.07 2.07,2.07, height 1.01
RGT0016C#1 [mm] "QFN, 16-Leads, Body 3x3mm, Pitch 0.5mm, Thermal Pad 1.7x1.7mm, TI Recommended"
  rrect40% 0.6x0.25 smd: 1(-1.4,0.75) 2(-1.4,0.25) 3(-1.4,-0.25) 4(-1.4,-0.75) 9(1.4,-0.75) 10(1.4,-0.25) 11(1.4,0.25) 12(1.4,0.75)
  rrect40% 0.25x0.6 smd: 5(-0.75,-1.4) 6(-0.25,-1.4) 7(0.25,-1.4) 8(0.75,-1.4) 13(0.75,1.4) 14(0.25,1.4) 15(-0.25,1.4) 16(-0.75,1.4)
  rrect6% 1.55x1.55 on Top Paste: 17(0,0)
  rrect6% 1.7x1.7 smd paste-0.85: 17(0,0)
  silkscreen extent -1.73,-1.73 1.72,1.73, body extent -1.57,-1.57 1.58,1.58, height 1.01
RGT0016C#2 [mm] "QFN, 16-Leads, Body 3x3mm, Pitch 0.5mm, Thermal Pad 1.7x1.7mm, TI Recommended"
  rrect40% 0.6x0.25 smd: 1(-1.4,0.75) 2(-1.4,0.25) 3(-1.4,-0.25) 4(-1.4,-0.75) 9(1.4,-0.75) 10(1.4,-0.25) 11(1.4,0.25) 12(1.4,0.75)
  rrect40% 0.25x0.6 smd: 5(-0.75,-1.4) 6(-0.25,-1.4) 7(0.25,-1.4) 8(0.75,-1.4) 13(0.75,1.4) 14(0.25,1.4) 15(-0.25,1.4) 16(-0.75,1.4)
  rrect6% 1.55x1.55 on Bottom Paste: 17(0,0)
  rrect6% 1.7x1.7 smd paste-0.85: 17(0,0)
  silkscreen extent -1.72,-1.73 1.72,1.73, body extent -1.57,-1.57 1.58,1.58, height 1.01
RGZ0048A [mm] "QFN, 48-Leads, Body 7x7mm, Pitch 0.5mm, Thermal Pad 5.15X5.15mm, TI recommended"
  oval 0.24x0.6 smd rot 45: 1(0.46,-4.349) 2(0.813,-3.995) 3(1.167,-3.642) 4(1.52,-3.288) 5(1.874,-2.934) 6(2.227,-2.581) 7(2.581,-2.227) 8(2.934,-1.874) 9(3.288,-1.52) 10(3.642,-1.167) 11(3.995,-0.813) 12(4.349,-0.46) 25(-0.46,4.349) 26(-0.813,3.995) 27(-1.167,3.642) 28(-1.52,3.288) 29(-1.874,2.934) 30(-2.227,2.581) 31(-2.581,2.227) 32(-2.934,1.874) 33(-3.288,1.52) 34(-3.642,1.167) 35(-3.995,0.813) 36(-4.349,0.46)
  oval 0.24x0.6 smd rot 135: 13(4.349,0.46) 14(3.995,0.813) 15(3.642,1.167) 16(3.288,1.52) 17(2.934,1.874) 18(2.581,2.227) 19(2.227,2.581) 20(1.874,2.934) 21(1.52,3.288) 22(1.167,3.642) 23(0.813,3.995) 24(0.46,4.349) 37(-4.349,-0.46) 38(-3.995,-0.813) 39(-3.642,-1.167) 40(-3.288,-1.52) 41(-2.934,-1.874) 42(-2.581,-2.227) 43(-2.227,-2.581) 44(-1.874,-2.934) 45(-1.52,-3.288) 46(-1.167,-3.642) 47(-0.813,-3.995) 48(-0.46,-4.349)
  rect 5.15x5.15 smd rot 135 paste-2.6: 49(0,0)
  silkscreen extent -5.27,-5.27 5.27,5.27, body extent -5.06,-5.06 5.06,5.06, height 1.01
RUT0012A [mm] "QFN, 12-Leads, Body 1.7x2mm, Pitch 0.4mm, TI Recommended"
  rrect50% 0.7x0.2 smd: 1(-0.7,0.8) 2(-0.7,0.4) 3(-0.7,0) 4(-0.7,-0.4) 5(-0.7,-0.8) 7(0.7,-0.8) 8(0.7,-0.4) 9(0.7,0) 10(0.7,0.4) 11(0.7,0.8)
  rrect50% 0.2x0.7 smd: 6(0,-0.85) 12(0,0.85)
  silkscreen extent -1.07,-1.2 0.9,1.23, body extent -0.9,-1.05 0.9,1.05, height 0.56
SOD-523F [mm] "COMCHIP"
  rect 0.6x0.8 smd paste-0.05: 1(-0.85,0) 2(0.85,0)
  silkscreen extent -1.92,-0.87 1.1,0.87, body extent -0.9,-0.5 0.9,0.5, height 0.85
SOT-23 [mm] "SOT23, 3-Leads, Body 2.9x1.3mm, Pitch 0.95mm, Lead Span 2.5mm, IPC Medium Density"
  rrect50% 0.6x1 smd: 1(0.32,-0.946) 2(2.22,-0.946) 3(1.27,1.454)
  silkscreen extent -0.23,-1.37 2.77,0.95, body extent -0.18,-0.91 2.72,1.46, height 1
SW_B3U-1000P [mm] "OMRON"
  rect 0.8x1.7 smd: 1(-1.7,0) 2(1.7,0)
  silkscreen extent -1.5,-1.25 1.5,1.25, body extent -1.5,-1.25 1.5,1.25, height 1.75
SW_GS-113-0043 [mm] "TH, 6-Leads, Body 9.65x7.92mm, Pitch 3.05mm"
  round 1.85 hole 1.35: 1(-3.05,1.675) 2(0,1.675) 3(3.05,1.675) 4(-3.05,-1.675) 5(0,-1.675) 6(3.05,-1.675)
  silkscreen extent -4.83,-4.09 4.82,4.5, body extent -4.82,-4.09 4.82,4.09, height 11.17
TP_H045P075 [mm] "TP_H0.45P0.75"
  round 0.75 hole 0.45: 1(0,0)
TP_SM_1MM [mm] "1mm Test Point, SMT"
  round 1 smd paste-0.5: 1(0,0)
YZF0009-C01 [mm] "BGA, 9-Leads, Body 1.6205x1.58mm, Pitch 0.5mm"
  round 0.245 smd paste-0.15: A1(-0.5,0.5) A2(0,0.5) A3(0.5,0.5) B1(-0.5,0) B2(0,0) B3(0.5,0) C1(-0.5,-0.5) C2(0,-0.5) C3(0.5,-0.5)
  silkscreen extent -0.92,-0.9 0.92,0.9, body extent -0.82,-0.8 0.82,0.8, height 0.63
